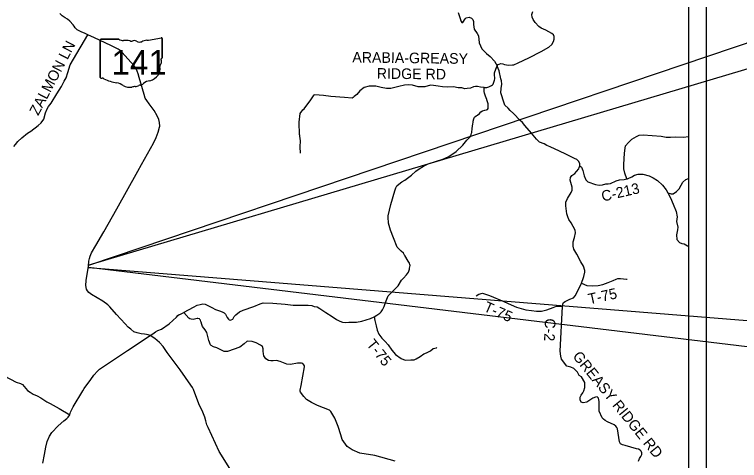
# Model space of a CAD drawing. Extents: x 0 to 34, y 0 to 22.
# Drawn here: x 5.084 to 9.19, y 16.922 to 19.448 of the extents above; entities that cross this region are included whole.
import ezdxf

# ---------------------------------------------------------------- set-up
doc = ezdxf.new("R2010")
doc.units = 0
for name, color, linetype in [('GM_X_County_Road', 7, 'Continuous'), ('GM_X_County_Road_Text', 7, 'Continuous'), ('GM_X_State_Route', 7, 'Continuous'), ('GM_X_State_Shield', 7, 'Continuous'), ('GM_X_Township_Road', 7, 'Continuous'), ('GM_X_Township_Road_Text', 7, 'Continuous'), ('SH_Data', 7, 'Continuous'), ('SH_Masking', 7, 'Continuous'), ('SH_Text', 7, 'Continuous')]:
    doc.layers.add(name, color=color, linetype=linetype)

msp = doc.modelspace()

# ---------------------------------------------------------------- linework, layer by layer
at = {"layer": 'GM_X_County_Road'}
for points in [[(8.2824, 18.5813), (8.2853, 18.5904), (8.2845, 18.6033), (8.2772, 18.6177), (8.2677, 18.6268), (8.2555, 18.6324), (8.2058, 18.6569), (8.1708, 18.6746), (8.1176, 18.6978), (8.0982, 18.7065), (8.083, 18.7148), (8.0572, 18.7241), (8.04, 18.7415), (8.0114, 18.7748), (7.9733, 18.8191), (7.9611, 18.8353), (7.9477, 18.847), (7.91, 18.8864), (7.8902, 18.9041), (7.8787, 18.9181), (7.8616, 18.9347), (7.8504, 18.962), (7.8431, 18.9867), (7.8377, 19.0049), (7.8398, 19.0277), (7.8431, 19.0531), (7.8415, 19.0714), (7.8376, 19.0843), (7.8279, 19.1283), (7.8236, 19.1415), (7.8175, 19.1566)], [(8.6179, 16.9174), (8.6233, 16.9322), (8.6313, 16.9436), (8.6363, 16.955), (8.6371, 16.9648), (8.6326, 16.9747), (8.6262, 16.9808), (8.6183, 16.985), (8.6073, 16.9881), (8.5422, 17.0056), (8.5267, 17.0102), (8.5161, 17.0156), (8.5104, 17.0266), (8.4991, 17.1003), (8.4954, 17.1087), (8.4886, 17.1163), (8.4803, 17.1228), (8.4425, 17.1401), (8.4281, 17.1474), (8.4187, 17.1562), (8.4115, 17.1638), (8.3958, 17.2015), (8.3952, 17.2262), (8.3942, 17.2558), (8.392, 17.2737), (8.3837, 17.2825), (8.3746, 17.281), (8.3594, 17.2739), (8.3244, 17.2524), (8.305, 17.2491), (8.2926, 17.2525), (8.2873, 17.2647), (8.2878, 17.2807), (8.2935, 17.292), (8.302, 17.3053), (8.3077, 17.3167), (8.3145, 17.3343), (8.3136, 17.3635), (8.2956, 17.3945), (8.2826, 17.4036), (8.2723, 17.4214), (8.2517, 17.4418), (8.2346, 17.4493), (8.2111, 17.4568), (8.1821, 17.4958), (8.177, 17.5132), (8.175, 17.5417), (8.1868, 17.7932), (8.1894, 17.8076), (8.1928, 17.8156), (8.2018, 17.8217), (8.2287, 17.8348), (8.2498, 17.8428), (8.2592, 17.8543), (8.2716, 17.8786), (8.294, 17.9265), (8.2967, 17.9323), (8.3045, 17.9525), (8.3079, 17.9646), (8.3142, 17.9878), (8.3137, 17.9977), (8.306, 18.0216), (8.2915, 18.047), (8.2681, 18.0898), (8.2513, 18.1182), (8.2474, 18.1356), (8.2484, 18.1592), (8.2547, 18.1854), (8.2617, 18.2105), (8.2598, 18.2268), (8.2372, 18.2677), (8.223, 18.2874), (8.2173, 18.3011), (8.2111, 18.3189), (8.207, 18.3648), (8.2069, 18.3846), (8.2148, 18.4047), (8.2366, 18.4402), (8.2425, 18.4535), (8.2417, 18.4702), (8.2301, 18.51), (8.2319, 18.5241), (8.2406, 18.5363), (8.2564, 18.5477), (8.267, 18.5577), (8.2801, 18.5744), (8.2823, 18.581), (8.2824, 18.5813)], [(8.2853, 18.5904), (8.2941, 18.5825), (8.3018, 18.5647), (8.3099, 18.5339), (8.3195, 18.5116), (8.3306, 18.5006), (8.3746, 18.4845), (8.394, 18.4804), (8.4144, 18.4839), (8.4326, 18.4893), (8.4466, 18.4882), (8.4595, 18.4913), (8.4916, 18.5056), (8.5105, 18.511), (8.537, 18.5141), (8.5509, 18.5165), (8.5548, 18.5172), (8.5552, 18.5172)], [(8.5552, 18.5172), (8.5598, 18.518), (8.579, 18.5287), (8.5949, 18.5379), (8.6153, 18.5437), (8.6419, 18.5442), (8.6772, 18.5334), (8.7003, 18.5229), (8.7247, 18.507), (8.7544, 18.4802), (8.7742, 18.4549), (8.7838, 18.4386), (8.7991, 18.409), (8.8145, 18.3726), (8.831, 18.3317), (8.8373, 18.3021), (8.8339, 18.2884), (8.8321, 18.2759), (8.8399, 18.244), (8.8381, 18.228), (8.8322, 18.1999), (8.835, 18.1737), (8.8495, 18.1559), (8.8624, 18.1511), (8.8768, 18.1489), (8.8954, 18.1383), (8.9, 18.1359)]]:
    msp.add_lwpolyline(points, dxfattribs=at)
at = {"layer": 'GM_X_State_Route'}
for points in [[(7.7585, 18.9665), (7.7514, 18.9852), (7.7459, 19.0016), (7.7442, 19.0123), (7.7439, 19.021), (7.7439, 19.024), (7.7437, 19.0339), (7.7509, 19.0342), (7.7585, 19.0348), (7.7696, 19.0373), (7.7856, 19.0454), (7.7902, 19.0496), (7.7941, 19.0541), (7.7992, 19.065), (7.8027, 19.0767), (7.8036, 19.0843), (7.8033, 19.0915), (7.8031, 19.1021), (7.8028, 19.1086), (7.8029, 19.1173), (7.8089, 19.1377), (7.8175, 19.1566), (7.823, 19.1641), (7.8287, 19.1674), (7.8382, 19.1696), (7.8492, 19.169), (7.8597, 19.1647), (7.8696, 19.1619), (7.8817, 19.161), (7.9033, 19.1622), (7.9113, 19.1636), (7.9361, 19.1734), (7.9975, 19.2021), (8.0663, 19.2376), (8.1103, 19.2631), (8.1264, 19.2784), (8.1369, 19.2954), (8.1405, 19.3075), (8.1396, 19.3231), (8.1355, 19.3318), (8.1269, 19.3399), (8.0934, 19.3583), (8.0667, 19.3708), (8.0528, 19.3801), (8.0319, 19.4017), (8.0212, 19.4193), (8.0157, 19.4331), (8.014, 19.4471), (8.0188, 19.4653)], [(5.9026, 18.8027), (5.9028, 18.8035), (5.906, 18.8151), (5.9052, 18.8368), (5.9013, 18.8532), (5.8921, 18.8742), (5.8744, 18.9033), (5.8465, 18.9424), (5.8335, 18.9608), (5.8246, 18.9746), (5.8173, 18.9941), (5.7891, 19.0909), (5.7838, 19.1126), (5.7787, 19.1272), (5.7702, 19.1436), (5.7561, 19.1651), (5.7501, 19.171), (5.7449, 19.1762), (5.6923, 19.234), (5.6822, 19.2444), (5.6717, 19.251), (5.6299, 19.2717), (5.5377, 19.3148), (5.4989, 19.3329), (5.4831, 19.3407), (5.462, 19.3505), (5.4461, 19.3572), (5.439, 19.3603), (5.4345, 19.3642), (5.4278, 19.3726), (5.4222, 19.3818), (5.4163, 19.3895), (5.3976, 19.4091), (5.3845, 19.4207), (5.371, 19.4293), (5.3537, 19.4409), (5.3414, 19.4536)], [(7.6728, 18.7749), (7.674, 18.7787), (7.6755, 18.8015), (7.6801, 18.8291), (7.6808, 18.8361), (7.6814, 18.8431), (7.685, 18.8571), (7.6897, 18.8665), (7.6978, 18.8729), (7.7066, 18.8769), (7.7169, 18.8874), (7.7243, 18.8964), (7.7342, 18.9012), (7.7468, 18.9059), (7.7567, 18.9081), (7.762, 18.9103), (7.7659, 18.9148), (7.7671, 18.9223), (7.7659, 18.9413), (7.7626, 18.9524), (7.7594, 18.9642), (7.7585, 18.9665)], [(5.8025, 18.5981), (5.803, 18.599), (5.8701, 18.7188), (5.8854, 18.7505), (5.8969, 18.7822), (5.9026, 18.8027)], [(7.3214, 18.0108), (7.3245, 18.0254), (7.3231, 18.0322), (7.3202, 18.0398), (7.3124, 18.0513), (7.2939, 18.0827), (7.2924, 18.085), (7.2872, 18.095), (7.2742, 18.1081), (7.2611, 18.12), (7.2514, 18.1308), (7.2305, 18.1827), (7.2137, 18.2259), (7.2021, 18.2655), (7.1992, 18.3001), (7.1997, 18.3073), (7.2158, 18.3709), (7.2378, 18.4495), (7.2434, 18.4661), (7.2496, 18.4774), (7.2596, 18.4875), (7.2765, 18.4998), (7.2944, 18.5094), (7.3101, 18.5202), (7.332, 18.5381), (7.3562, 18.5598), (7.375, 18.5735), (7.3998, 18.5887), (7.4258, 18.6013), (7.4742, 18.6173), (7.51, 18.6289), (7.539, 18.6425), (7.5719, 18.6618), (7.5857, 18.6714), (7.6237, 18.7085), (7.6461, 18.7351), (7.663, 18.7527), (7.6685, 18.7609), (7.6728, 18.7749)], [(5.8516, 17.6287), (5.8403, 17.6336), (5.8315, 17.6351), (5.8202, 17.6373), (5.8011, 17.6395), (5.7789, 17.6444), (5.7604, 17.6512), (5.7424, 17.6646), (5.7276, 17.6775), (5.7104, 17.6962), (5.6619, 17.749), (5.6239, 17.7927), (5.6124, 17.8036), (5.5836, 17.8235), (5.5195, 17.8627), (5.5056, 17.8732), (5.4974, 17.8824), (5.4919, 17.8927), (5.4876, 17.9137), (5.4903, 17.9417), (5.5037, 18.0224), (5.5052, 18.0504), (5.5077, 18.0662), (5.5126, 18.0794), (5.519, 18.0972), (5.5436, 18.1395), (5.5893, 18.2172), (5.6634, 18.3476), (5.7818, 18.5611), (5.8025, 18.5981)], [(6.6796, 17.8013), (6.7062, 17.8013), (6.7283, 17.8018), (6.747, 17.8007), (6.7683, 17.7987), (6.7816, 17.7946), (6.797, 17.791), (6.8134, 17.7825), (6.8469, 17.7607), (6.8832, 17.7377), (6.908, 17.7208), (6.9256, 17.7112), (6.9415, 17.7055), (6.9597, 17.7038), (6.9767, 17.7049), (7.0201, 17.7045), (7.05, 17.7101), (7.1002, 17.7253), (7.1205, 17.7349), (7.1354, 17.7449), (7.1523, 17.7564), (7.1603, 17.7639), (7.1681, 17.7744), (7.1767, 17.7929), (7.1878, 17.8258), (7.1968, 17.845), (7.2007, 17.8541), (7.2061, 17.8608), (7.2188, 17.8735), (7.2461, 17.8997), (7.2557, 17.9113), (7.2748, 17.9422), (7.2867, 17.9538), (7.3037, 17.9737), (7.3145, 17.9879), (7.32, 18.0045), (7.3214, 18.0108)], [(5.8516, 17.6287), (5.8673, 17.6393), (5.8822, 17.6512), (5.8964, 17.6571), (5.9158, 17.6651), (5.9602, 17.6956), (6.0021, 17.7333), (6.0091, 17.7424), (6.016, 17.7479), (6.0236, 17.7509), (6.0423, 17.7605), (6.0438, 17.7616), (6.0966, 17.7897), (6.1191, 17.8007), (6.1351, 17.8058), (6.1507, 17.8086), (6.1628, 17.8073), (6.1752, 17.8022), (6.2019, 17.7889), (6.2226, 17.7776), (6.2502, 17.768), (6.263, 17.7625), (6.272, 17.7575), (6.2791, 17.7498), (6.2891, 17.7322), (6.295, 17.723), (6.3002, 17.718), (6.3051, 17.7164), (6.3112, 17.7174), (6.3206, 17.7222), (6.3286, 17.7374), (6.3382, 17.747), (6.3572, 17.7639), (6.3782, 17.7731), (6.4399, 17.794), (6.4751, 17.8082), (6.4926, 17.814), (6.5465, 17.8131), (6.6163, 17.8067), (6.6628, 17.8013), (6.6796, 17.8013)], [(5.2446, 16.9056), (5.2543, 16.9547), (5.2607, 16.9971), (5.2695, 17.0295), (5.2821, 17.0591), (5.2959, 17.08), (5.3307, 17.1174), (5.3641, 17.1461), (5.3799, 17.1594), (5.3881, 17.1679), (5.3965, 17.181), (5.4014, 17.1953), (5.4166, 17.226), (5.4703, 17.3168), (5.4787, 17.3303), (5.5155, 17.3807), (5.5337, 17.4055), (5.553, 17.4276), (5.5649, 17.438), (5.5821, 17.4507), (5.7241, 17.5446), (5.8516, 17.6287)], [(6.3215, 16.8466), (6.2435, 16.9728), (6.1804, 17.108), (6.1737, 17.1236), (6.1673, 17.1455), (6.162, 17.1675), (6.15, 17.1958), (6.1285, 17.2416), (6.0982, 17.323), (6.0924, 17.335), (6.0832, 17.3485), (6.0214, 17.4356), (5.9493, 17.5334), (5.9257, 17.5673), (5.9052, 17.5908), (5.8786, 17.6124), (5.8516, 17.6287)]]:
    msp.add_lwpolyline(points, dxfattribs=at)
at = {"layer": 'GM_X_State_Shield'}
for p, q in [((5.5695, 19.3038), (5.5695, 19.0912)), ((5.6755, 19.3075), (5.5729, 19.3075)), ((5.9196, 19.2015), (5.9196, 19.3127)), ((5.9196, 19.2016), (5.9196, 19.2015))]:
    msp.add_line(p, q, dxfattribs=at)
for centre, major_axis, start_param, end_param in [((5.5735, 19.3043), (0.00406, 0), 1.712693, 3.28349), ((5.6999, 19.3321), (0.0393, 0), 4.042523, 4.731795), ((5.7129, 19.1881), (0.1412, 0), 1.404758, 1.657858), ((5.745, 19.3054), (0.0113, 0), 3.836095, 5.185415), ((5.7617, 19.2808), (0.0236, 0), 0.950623, 2.079405), ((5.8422, 19.2425), (0.0747, 0), 1.699011, 2.107814), ((5.7949, 19.5973), (0.3713, 0), 4.814394, 5.042369), ((5.9157, 19.3132), (0.0039, 0), 6.141152, 7.989035), ((5.7921, 19.3145), (0.0284, 0), 4.081561, 5.145723), ((5.9187, 19.1934), (0.00603, 0), 1.883978, 3.671073), ((5.8803, 19.1793), (0.0362, 0), 5.934695, 6.695948), ((5.9154, 19.2011), (0.00417, 0), 5.05454, 6.418171), ((5.8157, 19.1408), (0.0929, 0), 5.101752, 6.440018), ((5.9336, 19.155), (0.0263, 0), 2.387724, 3.262537), ((5.5735, 19.0908), (0.00409, 0), 3.00124, 4.508301), ((5.5742, 19.1125), (0.0312, 0), 4.665946, 4.897461), ((5.5806, 19.079), (0.0113, 0), 0.519207, 1.627899), ((5.7227, 19.27), (0.2681, 0), 4.195997, 4.488961), ((5.6428, 18.9957), (0.0839, 0), 0.823519, 1.323587), ((5.7904, 19.0706), (0.03, 0), 4.937069, 5.64225), ((5.8548, 19.0316), (0.0509, 0), 1.647645, 2.488434), ((5.7335, 19.0779), (0.0532, 0), 4.026481, 4.996735), ((5.7643, 19.0044), (0.0437, 0), 1.495662, 1.94098), ((5.7681, 19.062), (0.0284, 0), 4.691044, 5.507374), ((5.7938, 19.0414), (0.00798, 0), 1.147584, 2.315152)]:
    msp.add_ellipse(centre, major_axis=major_axis, ratio=0.8, start_param=start_param, end_param=end_param, dxfattribs=at)
at = {"layer": 'GM_X_Township_Road'}
for points in [[(7.5956, 19.4591), (7.6013, 19.4416), (7.6079, 19.4257), (7.6117, 19.4113), (7.6171, 19.4022), (7.6232, 19.403), (7.6352, 19.4232), (7.6416, 19.4297), (7.6579, 19.4328), (7.6723, 19.4264), (7.6788, 19.4204), (7.6841, 19.409), (7.6835, 19.3915), (7.6863, 19.3653), (7.7035, 19.34), (7.7108, 19.3275), (7.7148, 19.2872), (7.7305, 19.2539), (7.7572, 19.2274), (7.7785, 19.2101), (7.8022, 19.184), (7.8175, 19.1566)], [(5.0795, 18.7), (5.089, 18.7114), (5.1024, 18.7288), (5.1248, 18.7493), (5.1583, 18.7747), (5.1765, 18.7875), (5.2187, 18.8182), (5.2354, 18.8345), (5.2492, 18.8554), (5.2602, 18.8899), (5.2686, 18.9135), (5.2759, 18.926), (5.2907, 18.9449), (5.3243, 18.9977), (5.3494, 19.0409), (5.3654, 19.0705), (5.3772, 19.0887), (5.3856, 19.1187), (5.3998, 19.1628), (5.4177, 19.1954), (5.4989, 19.3329)], [(7.7437, 19.0339), (7.7227, 19.0366), (7.7052, 19.0392), (7.6938, 19.0395), (7.6832, 19.0376), (7.6658, 19.0314), (7.648, 19.0279), (7.6348, 19.0274), (7.6166, 19.0331), (7.5957, 19.0322), (7.5707, 19.0374), (7.5343, 19.0361), (7.5081, 19.0382), (7.4839, 19.0419), (7.4562, 19.0456), (7.4406, 19.0466), (7.4073, 19.0385), (7.3891, 19.0373), (7.3698, 19.0387), (7.3372, 19.0469), (7.3163, 19.0502), (7.2917, 19.0478), (7.2603, 19.04), (7.2145, 19.028), (7.1898, 19.0287), (7.1606, 19.0335), (7.1295, 19.0417), (7.0924, 19.0415), (7.0636, 19.0338), (7.0402, 19.0147), (7.0233, 18.9941), (7.0067, 18.9826), (7.001, 18.9769), (6.996, 18.9747), (6.9529, 18.9778), (6.8754, 18.9834), (6.8341, 18.9885), (6.8088, 18.991), (6.7812, 18.9936)], [(6.7027, 18.6617), (6.7014, 18.6975), (6.7013, 18.7), (6.7014, 18.7019), (6.7014, 18.7036), (6.7016, 18.7058), (6.7032, 18.7249), (6.7034, 18.7265), (6.7034, 18.728), (6.7034, 18.7292), (6.7033, 18.7304), (6.7033, 18.7315), (6.7031, 18.7329), (6.6996, 18.758), (6.6994, 18.7591), (6.6992, 18.7606), (6.699, 18.763), (6.6988, 18.7648), (6.6987, 18.7665), (6.695, 18.8372), (6.701, 18.8866), (6.7175, 18.9084), (6.7251, 18.9134), (6.7614, 18.9652), (6.7812, 18.9936)], [(8.5509, 18.5165), (8.5411, 18.5489), (8.5351, 18.5743), (8.534, 18.5979), (8.5363, 18.6298), (8.5387, 18.6621), (8.5418, 18.691), (8.5449, 18.7043), (8.5608, 18.7221), (8.5806, 18.7414), (8.6057, 18.7569), (8.622, 18.7652), (8.6444, 18.7667), (8.7457, 18.7581), (8.7738, 18.7535), (8.7989, 18.7523), (8.8262, 18.7548), (8.8721, 18.7524), (8.9, 18.7562)], [(8.7838, 18.4386), (8.8019, 18.4323), (8.8133, 18.4327), (8.8331, 18.4459), (8.8483, 18.4596), (8.8589, 18.4812), (8.8688, 18.4983), (8.8852, 18.5134), (8.9, 18.5196)], [(8.294, 17.9265), (8.3259, 17.9126), (8.3566, 17.9102), (8.3885, 17.9136), (8.4151, 17.9192), (8.4462, 17.9297), (8.4736, 17.9415), (8.4918, 17.9494), (8.5002, 17.9524), (8.5161, 17.9524), (8.5506, 17.9485), (8.5537, 17.9478)], [(7.6978, 17.8543), (7.7132, 17.8632), (7.7338, 17.8692), (7.774, 17.8569), (7.8551, 17.8225), (7.8972, 17.8042), (7.9275, 17.7901), (7.954, 17.7824), (7.9798, 17.7755), (8.0121, 17.7705), (8.0398, 17.7674), (8.0675, 17.7677), (8.099, 17.7752), (8.1351, 17.788), (8.1533, 17.7952), (8.1632, 17.7963), (8.1868, 17.7932)], [(7.24, 16.917), (7.1241, 16.9504), (7.0404, 16.9633), (6.996, 16.9827), (6.9677, 17.0006), (6.9404, 17.0397), (6.931, 17.0677), (6.9173, 17.1144), (6.8985, 17.1618), (6.8745, 17.1987), (6.8673, 17.2065), (6.7992, 17.2325), (6.765, 17.2508), (6.7374, 17.2677), (6.7215, 17.2844), (6.7041, 17.3077), (6.7023, 17.3144), (6.7014, 17.3195), (6.708, 17.3464), (6.7267, 17.4529), (6.7257, 17.4574), (6.723, 17.4642), (6.7174, 17.4701), (6.7083, 17.4729), (6.6874, 17.4726), (6.6474, 17.465), (6.6259, 17.4671), (6.5884, 17.4819), (6.5682, 17.4878), (6.5495, 17.4855), (6.535, 17.4862), (6.5217, 17.4872), (6.508, 17.497), (6.4958, 17.5149), (6.494, 17.5249), (6.4922, 17.5401), (6.492, 17.5534), (6.4882, 17.5669), (6.4826, 17.5712), (6.4779, 17.5748), (6.4528, 17.5876), (6.4303, 17.5957), (6.402, 17.5969), (6.3837, 17.583), (6.3592, 17.5628), (6.2895, 17.5382), (6.2845, 17.5382), (6.2713, 17.5383), (6.2304, 17.5598), (6.2107, 17.5655), (6.1984, 17.5734), (6.1934, 17.5766), (6.1838, 17.6005), (6.1723, 17.647), (6.1629, 17.6624), (6.149, 17.6799), (6.1447, 17.6917), (6.1415, 17.7052), (6.1399, 17.7098), (6.1377, 17.7157), (6.1343, 17.7197), (6.1306, 17.7238), (6.1293, 17.7243), (6.1228, 17.7262), (6.1211, 17.7265), (6.1179, 17.7256), (6.0959, 17.7207), (6.0845, 17.7217), (6.076, 17.724), (6.0713, 17.728), (6.0423, 17.7605)], [(7.1205, 17.7349), (7.125, 17.7148), (7.1322, 17.684), (7.1374, 17.6597), (7.1476, 17.638), (7.1639, 17.6136), (7.1824, 17.5954), (7.1998, 17.5775), (7.2199, 17.5466), (7.2411, 17.5219), (7.2744, 17.4987), (7.2968, 17.4906), (7.3283, 17.4917), (7.3477, 17.4924), (7.359, 17.4966), (7.3819, 17.5109), (7.4028, 17.5265), (7.4172, 17.5314), (7.4404, 17.5435), (7.4548, 17.5552), (7.4731, 17.559), (7.476, 17.5636)], [(5.026, 17.4018), (5.0934, 17.3655), (5.1177, 17.3579), (5.1287, 17.3514), (5.1393, 17.3415), (5.1575, 17.3175), (5.1722, 17.3092), (5.1904, 17.2966), (5.2116, 17.2885), (5.2331, 17.2762), (5.2493, 17.2655), (5.2671, 17.254), (5.2856, 17.2448), (5.3374, 17.2157), (5.3965, 17.181)]]:
    msp.add_lwpolyline(points, dxfattribs=at)
at = {"layer": 'SH_Data'}
for p, q in [((9, 21), (9, 14)), ((8.9, 20.9), (8.9, 14.1))]:
    msp.add_line(p, q, dxfattribs=at)
at = {"layer": 'SH_Masking'}
for p, q in [((5.5695, 19.0912), (5.5695, 19.3038)), ((5.5729, 19.3075), (5.6755, 19.3075)), ((5.9196, 19.3127), (5.9196, 19.2015)), ((5.9168, 19.198), (5.9168, 19.198))]:
    msp.add_line(p, q, dxfattribs=at)
for centre, major_axis, start_param, end_param in [((5.5735, 19.3043), (0.00406, 0), 1.712693, 3.28349), ((5.6999, 19.3321), (0.0393, 0), 4.042523, 4.731795), ((5.7129, 19.1881), (0.1412, 0), 1.404758, 1.657858), ((5.745, 19.3054), (0.0113, 0), 3.836095, 5.185415), ((5.7617, 19.2808), (0.0236, 0), 0.950623, 2.079405), ((5.8422, 19.2425), (0.0747, 0), 1.699011, 2.107814), ((5.7949, 19.5973), (0.3713, 0), 4.814394, 5.042369), ((5.9157, 19.3132), (0.0039, 0), 6.141152, 7.989035), ((5.7921, 19.3145), (0.0284, 0), 4.081561, 5.145723), ((5.9187, 19.1934), (0.00603, 0), 1.883978, 3.671073), ((5.8803, 19.1793), (0.0362, 0), 5.934695, 6.695948), ((5.9154, 19.2011), (0.00417, 0), 5.05454, 6.418171), ((5.8157, 19.1408), (0.0929, 0), 5.101752, 6.440018), ((5.9336, 19.155), (0.0263, 0), 2.387724, 3.262537), ((5.5735, 19.0908), (0.00409, 0), 3.00124, 4.508301), ((5.5742, 19.1125), (0.0312, 0), 4.665946, 4.897461), ((5.5806, 19.079), (0.0113, 0), 0.519207, 1.627899), ((5.7227, 19.27), (0.2681, 0), 4.195997, 4.488961), ((5.6428, 18.9957), (0.0839, 0), 0.823519, 1.323587), ((5.7904, 19.0706), (0.03, 0), 4.937069, 5.64225), ((5.8548, 19.0316), (0.0509, 0), 1.647645, 2.488434), ((5.7335, 19.0779), (0.0532, 0), 4.026481, 4.996735), ((5.7643, 19.0044), (0.0437, 0), 1.495662, 1.94098), ((5.7681, 19.062), (0.0284, 0), 4.691044, 5.507374), ((5.7938, 19.0414), (0.00798, 0), 1.147584, 2.315152)]:
    msp.add_ellipse(centre, major_axis=major_axis, ratio=0.8, start_param=start_param, end_param=end_param, dxfattribs=at)
at = {"layer": 'SH_Text'}
for points in [[(5.504, 18.0282), (9.3067, 19.311), (9.3067, 19.1612)], [(5.5023, 18.0138), (9.28, 17.7105), (9.28, 17.5606)]]:
    msp.add_lwpolyline(points, close=True, dxfattribs=at)

# ---------------------------------------------------------------- texts
at = {"layer": 'GM_X_County_Road_Text'}
for s, rotation, p in [('ARABIA-GREASY', 359.2761, (6.9966, 19.1762)), ('RIDGE RD', 359.2761, (7.1349, 19.0844)), ('C-213', 12.9548, (8.4153, 18.3878)), ('C-2', 267.3063, (8.0886, 17.7277)), ('GREASY RIDGE RD', 309.0801, (8.2414, 17.5104))]:
    msp.add_text(s, height=0.06, rotation=rotation, dxfattribs=at).set_placement(p)
at = {"layer": 'GM_X_State_Shield'}
msp.add_text('141', height=0.14004, dxfattribs=at).set_placement((5.6334, 19.1062))
at = {"layer": 'GM_X_Township_Road_Text'}
for s, rotation, p in [('ZALMON LN', 62.3918, (5.2181, 18.8716)), ('T-75', 12.2989, (8.3395, 17.8056)), ('T-75', 336.4692, (7.736, 17.7698)), ('T-75', 308.8333, (7.0736, 17.5784))]:
    msp.add_text(s, height=0.06, rotation=rotation, dxfattribs=at).set_placement(p)

doc.saveas('drawing.dxf')
